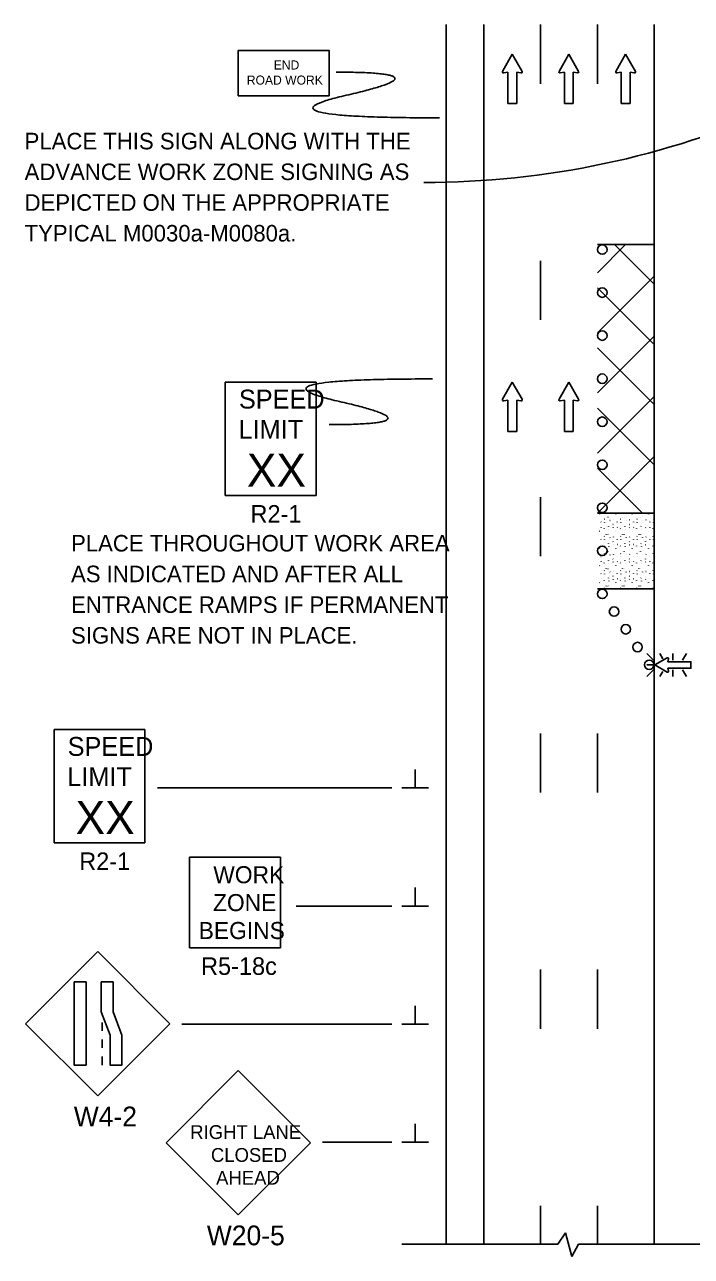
# Model space of a CAD drawing. Extents: x 16774 to 18475, y 7218 to 8206.
# Drawn here: x 16774 to 17056, y 7680 to 8201 of the extents above; entities that cross this region are included whole.
import ezdxf

# ---------------------------------------------------------------- set-up
doc = ezdxf.new("R2010")
doc.units = 0
for name, color, linetype in [('ALI_LEGAL_EX', 7, 'Continuous'), ('MT_SCRATCH_LEVEL_E', 7, 'Continuous'), ('PAVT_EDGE_EX', 7, 'Continuous'), ('TRAFFIC_SIGNS_PR', 7, 'Continuous'), ('TYPICAL_TEXT_DIMEN_PR', 7, 'Continuous')]:
    doc.layers.add(name, color=color, linetype=linetype)

msp = doc.modelspace()

# ---------------------------------------------------------------- linework, layer by layer
at = {"layer": 'ALI_LEGAL_EX'}
for points in [[(16992.01, 8201.21), (16992.01, 8176.21)], [(17016.01, 8201.21), (17016.01, 8176.21)], [(16992.01, 8101.21), (16992.01, 8076.21)], [(16992.01, 8001.21), (16992.01, 7976.21)], [(16992.01, 7901.21), (16992.01, 7876.21)], [(17016.01, 7901.21), (17016.01, 7876.21)], [(16992.01, 7801.21), (16992.01, 7776.21)], [(17016.01, 7801.21), (17016.01, 7776.21)], [(16992.01, 7701.21), (16992.01, 7684.99)], [(17016.01, 7701.21), (17016.01, 7684.99)]]:
    msp.add_lwpolyline(points, dxfattribs=at)
at = {"layer": 'MT_SCRATCH_LEVEL_E'}
for p, q in [((16980.01, 8188.68), (16975.89, 8181.44)), ((16984.15, 8181.44), (16980.01, 8188.68)), ((17003.91, 8188.68), (16999.8, 8181.44)), ((17008.06, 8181.44), (17003.91, 8188.68)), ((17027.96, 8188.68), (17023.85, 8181.44)), ((17032.11, 8181.44), (17027.96, 8188.68)), ((16976.38, 8180.75), (16978.15, 8181.07)), ((16978.15, 8181.07), (16978.15, 8167.81)), ((16981.9, 8167.81), (16981.9, 8181.07)), ((16981.9, 8181.07), (16983.67, 8180.75)), ((17000.28, 8180.75), (17002.06, 8181.07)), ((17002.06, 8181.07), (17002.06, 8167.81)), ((17005.8, 8167.81), (17005.8, 8181.07)), ((17005.8, 8181.07), (17007.58, 8180.75)), ((17024.33, 8180.75), (17026.11, 8181.07)), ((17026.11, 8181.07), (17026.11, 8167.81)), ((17029.85, 8167.81), (17029.85, 8181.07)), ((17029.85, 8181.07), (17031.63, 8180.75)), ((16978.15, 8167.81), (16981.9, 8167.81)), ((17002.06, 8167.81), (17005.8, 8167.81)), ((17026.11, 8167.81), (17029.85, 8167.81)), ((16980.01, 8049.9), (16975.89, 8042.66)), ((16984.15, 8042.66), (16980.01, 8049.9)), ((17003.91, 8049.9), (16999.8, 8042.66)), ((17008.06, 8042.66), (17003.91, 8049.9)), ((16976.38, 8041.98), (16978.15, 8042.29)), ((16978.15, 8042.29), (16978.15, 8029.04)), ((16981.9, 8029.04), (16981.9, 8042.29)), ((16981.9, 8042.29), (16983.67, 8041.98)), ((17000.28, 8041.98), (17002.06, 8042.29)), ((17002.06, 8042.29), (17002.06, 8029.04)), ((17005.8, 8029.04), (17005.8, 8042.29)), ((17005.8, 8042.29), (17007.58, 8041.98)), ((16978.15, 8029.04), (16981.9, 8029.04)), ((17002.06, 8029.04), (17005.8, 8029.04))]:
    msp.add_line(p, q, dxfattribs=at)
for centre, start, end in [((16976.3, 8181.21), 150.4248, 279.9638), ((16983.74, 8181.21), 260.0362, 29.7731), ((17000.21, 8181.21), 150.4248, 279.9638), ((17007.65, 8181.21), 260.0362, 29.7731), ((17024.26, 8181.21), 150.4248, 279.9638), ((17031.7, 8181.21), 260.0362, 29.7731), ((16976.3, 8042.44), 150.4248, 279.9638), ((16983.74, 8042.44), 260.0362, 29.7731), ((17000.21, 8042.44), 150.4248, 279.9638), ((17007.65, 8042.44), 260.0362, 29.7731)]:
    msp.add_arc(centre, 0.463, start, end, dxfattribs=at)
at = {"layer": 'PAVT_EDGE_EX'}
for p, q in [((16952.01, 8201.21), (16952.01, 7684.99)), ((16968.01, 8201.21), (16968.01, 7684.99)), ((17040.01, 8201.21), (17040.01, 7684.99)), ((17040.01, 8108.12), (17016.01, 8108.12)), ((17016.01, 8108.12), (17040.01, 8108.12)), ((17016.01, 8096.22), (17027.91, 8108.12)), ((17040.01, 8091.31), (17023.2, 8108.12)), ((17040.01, 7994.39), (17040.01, 8108.12)), ((17016.01, 8070.76), (17040.01, 8094.76)), ((17040.01, 8065.85), (17016.01, 8089.85)), ((17016.01, 8045.3), (17040.01, 8069.3)), ((17040.01, 8040.4), (17016.01, 8064.4)), ((17016.01, 8019.85), (17040.01, 8043.85)), ((17040.01, 8014.94), (17016.01, 8038.94)), ((17016.01, 7994.39), (17040.01, 8018.39)), ((17035.1, 7994.39), (17016.01, 8013.48)), ((17016.01, 7994.39), (17040.01, 7994.39)), ((17016.01, 7994.39), (17040.01, 7994.39)), ((17040.01, 7994.39), (17016.01, 7994.39)), ((17016.01, 7994.39), (17016.01, 7994.39)), ((17016.93, 7994.03), (17016.99, 7994.15)), ((17019.72, 7992.8), (17019.77, 7992.72)), ((17020.45, 7992.77), (17020.51, 7992.69)), ((17023.82, 7994.03), (17023.87, 7994.15)), ((17026.6, 7992.8), (17026.66, 7992.72)), ((17027.34, 7992.77), (17027.39, 7992.69)), ((17030.71, 7994.03), (17030.76, 7994.15)), ((17033.49, 7992.8), (17033.54, 7992.72)), ((17034.23, 7992.77), (17034.28, 7992.69)), ((17037.6, 7994.03), (17037.65, 7994.15)), ((17040.01, 7962.33), (17040.01, 7994.39)), ((17017.5, 7990.71), (17017.56, 7990.63)), ((17017.55, 7988.5), (17017.6, 7988.42)), ((17018.83, 7987.93), (17018.85, 7987.81)), ((17018.95, 7991.84), (17019.01, 7991.95)), ((17019.03, 7990.57), (17019.08, 7990.49)), ((17020.67, 7988.78), (17020.73, 7988.9)), ((17020.86, 7987.58), (17020.92, 7987.51)), ((17021.32, 7991.39), (17021.38, 7991.31)), ((17022.6, 7989.65), (17022.65, 7989.57)), ((17022.64, 7988.25), (17022.69, 7988.37)), ((17022.77, 7991.54), (17022.82, 7991.66)), ((17024.39, 7990.71), (17024.44, 7990.63)), ((17024.44, 7988.5), (17024.49, 7988.42)), ((17025.72, 7987.93), (17025.73, 7987.81)), ((17025.84, 7991.84), (17025.89, 7991.95)), ((17025.92, 7990.57), (17025.97, 7990.49)), ((17027.56, 7988.78), (17027.61, 7988.9)), ((17027.75, 7987.58), (17027.8, 7987.51)), ((17028.21, 7991.39), (17028.26, 7991.31)), ((17029.49, 7989.65), (17029.54, 7989.57)), ((17029.53, 7988.25), (17029.58, 7988.37)), ((17029.66, 7991.54), (17029.71, 7991.66)), ((17031.28, 7990.71), (17031.33, 7990.63)), ((17031.33, 7988.5), (17031.38, 7988.42)), ((17032.61, 7987.93), (17032.62, 7987.81)), ((17032.73, 7991.84), (17032.78, 7991.95)), ((17032.81, 7990.57), (17032.86, 7990.49)), ((17034.45, 7988.78), (17034.5, 7988.9)), ((17034.64, 7987.58), (17034.69, 7987.51)), ((17035.1, 7991.39), (17035.15, 7991.31)), ((17036.38, 7989.65), (17036.43, 7989.57)), ((17036.42, 7988.25), (17036.47, 7988.37)), ((17036.55, 7991.54), (17036.6, 7991.66)), ((17038.17, 7990.71), (17038.22, 7990.63)), ((17038.21, 7988.5), (17038.27, 7988.42)), ((17039.5, 7987.93), (17039.51, 7987.81)), ((17039.62, 7991.84), (17039.67, 7991.95)), ((17039.7, 7990.57), (17039.75, 7990.49)), ((17016.93, 7986.75), (17016.99, 7986.87)), ((17017.5, 7983.43), (17017.56, 7983.35)), ((17018.95, 7984.55), (17019.01, 7984.67)), ((17019.03, 7983.29), (17019.08, 7983.21)), ((17019.72, 7985.51), (17019.77, 7985.44)), ((17020.45, 7985.48), (17020.51, 7985.4)), ((17021.32, 7984.1), (17021.38, 7984.03)), ((17022.6, 7982.37), (17022.65, 7982.29)), ((17022.77, 7984.26), (17022.82, 7984.37)), ((17023.82, 7986.75), (17023.87, 7986.87)), ((17024.39, 7983.43), (17024.44, 7983.35)), ((17025.84, 7984.55), (17025.89, 7984.67)), ((17025.92, 7983.29), (17025.97, 7983.21)), ((17026.6, 7985.51), (17026.66, 7985.44)), ((17027.34, 7985.48), (17027.39, 7985.4)), ((17028.21, 7984.1), (17028.26, 7984.03)), ((17029.49, 7982.37), (17029.54, 7982.29)), ((17029.66, 7984.26), (17029.71, 7984.37)), ((17030.71, 7986.75), (17030.76, 7986.87)), ((17031.28, 7983.43), (17031.33, 7983.35)), ((17032.73, 7984.55), (17032.78, 7984.67)), ((17032.81, 7983.29), (17032.86, 7983.21)), ((17033.49, 7985.51), (17033.54, 7985.44)), ((17034.23, 7985.48), (17034.28, 7985.4)), ((17035.1, 7984.1), (17035.15, 7984.03)), ((17036.38, 7982.37), (17036.43, 7982.29)), ((17036.55, 7984.26), (17036.6, 7984.37)), ((17037.6, 7986.75), (17037.65, 7986.87)), ((17038.17, 7983.43), (17038.22, 7983.35)), ((17039.62, 7984.55), (17039.67, 7984.67)), ((17039.7, 7983.29), (17039.75, 7983.21)), ((17016.93, 7979.46), (17016.99, 7979.58)), ((17017.55, 7981.22), (17017.6, 7981.14)), ((17018.83, 7980.64), (17018.85, 7980.52)), ((17018.95, 7977.27), (17019.01, 7977.38)), ((17019.72, 7978.23), (17019.77, 7978.15)), ((17020.45, 7978.2), (17020.51, 7978.12)), ((17020.67, 7981.5), (17020.73, 7981.61)), ((17020.86, 7980.3), (17020.92, 7980.22)), ((17022.64, 7980.97), (17022.69, 7981.08)), ((17022.77, 7976.97), (17022.82, 7977.09)), ((17023.82, 7979.46), (17023.87, 7979.58)), ((17024.44, 7981.22), (17024.49, 7981.14)), ((17025.72, 7980.64), (17025.73, 7980.52)), ((17025.84, 7977.27), (17025.89, 7977.38)), ((17026.6, 7978.23), (17026.66, 7978.15)), ((17027.34, 7978.2), (17027.39, 7978.12)), ((17027.56, 7981.5), (17027.61, 7981.61)), ((17027.75, 7980.3), (17027.8, 7980.22)), ((17029.53, 7980.97), (17029.58, 7981.08)), ((17029.66, 7976.97), (17029.71, 7977.09)), ((17030.71, 7979.46), (17030.76, 7979.58)), ((17031.33, 7981.22), (17031.38, 7981.14)), ((17032.61, 7980.64), (17032.62, 7980.52)), ((17032.73, 7977.27), (17032.78, 7977.38)), ((17033.49, 7978.23), (17033.54, 7978.15)), ((17034.23, 7978.2), (17034.28, 7978.12)), ((17034.45, 7981.5), (17034.5, 7981.61)), ((17034.64, 7980.3), (17034.69, 7980.22)), ((17036.42, 7980.97), (17036.47, 7981.08)), ((17036.55, 7976.97), (17036.6, 7977.09)), ((17037.6, 7979.46), (17037.65, 7979.58)), ((17038.21, 7981.22), (17038.27, 7981.14)), ((17039.5, 7980.64), (17039.51, 7980.52)), ((17039.62, 7977.27), (17039.67, 7977.38)), ((17016.93, 7972.18), (17016.99, 7972.3)), ((17017.5, 7976.14), (17017.56, 7976.06)), ((17017.55, 7973.93), (17017.6, 7973.85)), ((17018.83, 7973.36), (17018.85, 7973.24)), ((17019.03, 7976), (17019.08, 7975.92)), ((17020.67, 7974.21), (17020.73, 7974.33)), ((17020.86, 7973.01), (17020.92, 7972.94)), ((17021.32, 7976.82), (17021.38, 7976.74)), ((17022.6, 7975.08), (17022.65, 7975)), ((17022.64, 7973.68), (17022.69, 7973.8)), ((17023.82, 7972.18), (17023.87, 7972.3)), ((17024.39, 7976.14), (17024.44, 7976.06)), ((17024.44, 7973.93), (17024.49, 7973.85)), ((17025.72, 7973.36), (17025.73, 7973.24)), ((17025.92, 7976), (17025.97, 7975.92)), ((17027.56, 7974.21), (17027.61, 7974.33)), ((17027.75, 7973.01), (17027.8, 7972.94)), ((17028.21, 7976.82), (17028.26, 7976.74)), ((17029.49, 7975.08), (17029.54, 7975)), ((17029.53, 7973.68), (17029.58, 7973.8)), ((17030.71, 7972.18), (17030.76, 7972.3)), ((17031.28, 7976.14), (17031.33, 7976.06)), ((17031.33, 7973.93), (17031.38, 7973.85)), ((17032.61, 7973.36), (17032.62, 7973.24)), ((17032.81, 7976), (17032.86, 7975.92)), ((17034.45, 7974.21), (17034.5, 7974.33)), ((17034.64, 7973.01), (17034.69, 7972.94)), ((17035.1, 7976.82), (17035.15, 7976.74)), ((17036.38, 7975.08), (17036.43, 7975)), ((17036.42, 7973.68), (17036.47, 7973.8)), ((17037.6, 7972.18), (17037.65, 7972.3)), ((17038.17, 7976.14), (17038.22, 7976.06)), ((17038.21, 7973.93), (17038.27, 7973.85)), ((17039.5, 7973.36), (17039.51, 7973.24)), ((17039.7, 7976), (17039.75, 7975.92)), ((17017.5, 7968.86), (17017.56, 7968.78)), ((17017.55, 7966.65), (17017.6, 7966.57)), ((17018.95, 7969.98), (17019.01, 7970.1)), ((17019.03, 7968.72), (17019.08, 7968.64)), ((17019.72, 7970.94), (17019.77, 7970.86)), ((17020.45, 7970.91), (17020.51, 7970.84)), ((17020.67, 7966.93), (17020.73, 7967.04)), ((17021.32, 7969.53), (17021.38, 7969.46)), ((17022.6, 7967.8), (17022.65, 7967.72)), ((17022.64, 7966.4), (17022.69, 7966.51)), ((17022.77, 7969.69), (17022.82, 7969.8)), ((17024.39, 7968.86), (17024.44, 7968.78)), ((17024.44, 7966.65), (17024.49, 7966.57)), ((17025.84, 7969.98), (17025.89, 7970.1)), ((17025.92, 7968.72), (17025.97, 7968.64)), ((17026.6, 7970.94), (17026.66, 7970.86)), ((17027.34, 7970.91), (17027.39, 7970.84)), ((17027.56, 7966.93), (17027.61, 7967.04)), ((17028.21, 7969.53), (17028.26, 7969.46)), ((17029.49, 7967.8), (17029.54, 7967.72)), ((17029.53, 7966.4), (17029.58, 7966.51)), ((17029.66, 7969.69), (17029.71, 7969.8)), ((17031.28, 7968.86), (17031.33, 7968.78)), ((17031.33, 7966.65), (17031.38, 7966.57)), ((17032.73, 7969.98), (17032.78, 7970.1)), ((17032.81, 7968.72), (17032.86, 7968.64)), ((17033.49, 7970.94), (17033.54, 7970.86)), ((17034.23, 7970.91), (17034.28, 7970.84)), ((17034.45, 7966.93), (17034.5, 7967.04)), ((17035.1, 7969.53), (17035.15, 7969.46)), ((17036.38, 7967.8), (17036.43, 7967.72)), ((17036.42, 7966.4), (17036.47, 7966.51)), ((17036.55, 7969.69), (17036.6, 7969.8)), ((17038.17, 7968.86), (17038.22, 7968.78)), ((17038.21, 7966.65), (17038.27, 7966.57)), ((17039.62, 7969.98), (17039.67, 7970.1)), ((17039.7, 7968.72), (17039.75, 7968.64)), ((17016.01, 7962.33), (17040.01, 7962.33)), ((17016.01, 7962.33), (17040.01, 7962.33)), ((17016.93, 7964.89), (17016.99, 7965.01)), ((17018.83, 7966.07), (17018.85, 7965.95)), ((17018.95, 7962.7), (17019.01, 7962.81)), ((17019.72, 7963.66), (17019.77, 7963.58)), ((17020.45, 7963.63), (17020.51, 7963.55)), ((17020.86, 7965.73), (17020.92, 7965.65)), ((17022.77, 7962.4), (17022.82, 7962.52)), ((17023.82, 7964.89), (17023.87, 7965.01)), ((17025.72, 7966.07), (17025.73, 7965.95)), ((17025.84, 7962.7), (17025.89, 7962.81)), ((17026.6, 7963.66), (17026.66, 7963.58)), ((17027.34, 7963.63), (17027.39, 7963.55)), ((17027.75, 7965.73), (17027.8, 7965.65)), ((17029.66, 7962.4), (17029.71, 7962.52)), ((17030.71, 7964.89), (17030.76, 7965.01)), ((17032.61, 7966.07), (17032.62, 7965.95)), ((17032.73, 7962.7), (17032.78, 7962.81)), ((17033.49, 7963.66), (17033.54, 7963.58)), ((17034.23, 7963.63), (17034.28, 7963.55)), ((17034.64, 7965.73), (17034.69, 7965.65)), ((17036.55, 7962.4), (17036.6, 7962.52)), ((17037.6, 7964.89), (17037.65, 7965.01)), ((17039.5, 7966.07), (17039.51, 7965.95)), ((17039.62, 7962.7), (17039.67, 7962.81))]:
    msp.add_line(p, q, dxfattribs=at)
at = {"layer": 'TRAFFIC_SIGNS_PR'}
for p, q in [((16858.56, 8049.85), (16896.96, 8049.85)), ((16858.56, 8001.85), (16858.56, 8049.85)), ((16896.96, 8001.85), (16896.96, 8049.85)), ((16858.56, 8001.85), (16896.96, 8001.85)), ((17037, 7935.03), (17039.81, 7932.21)), ((17039.81, 7930.18), (17037, 7930.18)), ((17043.72, 7932.84), (17042.46, 7935.03)), ((17047.9, 7932.21), (17047.9, 7935.03)), ((17052.03, 7932.21), (17053.66, 7935.03)), ((17037, 7925.32), (17039.81, 7928.14)), ((17042.43, 7925.32), (17043.64, 7927.42)), ((17047.9, 7928.14), (17047.9, 7925.32)), ((17053.69, 7925.32), (17052.06, 7928.14)), ((16786.11, 7902.82), (16824.51, 7902.82)), ((16786.11, 7854.82), (16786.11, 7902.82)), ((16824.51, 7854.82), (16824.51, 7902.82)), ((16786.11, 7854.82), (16824.51, 7854.82)), ((16843.5, 7810.42), (16843.5, 7848.82)), ((16843.5, 7848.82), (16881.9, 7848.82)), ((16881.9, 7810.42), (16881.9, 7848.82)), ((16843.5, 7810.42), (16881.9, 7810.42)), ((16804.64, 7808.84), (16774.09, 7778.29)), ((16835.18, 7778.29), (16804.64, 7808.84)), ((16806.48, 7778.85), (16806.48, 7775.25)), ((16774.09, 7778.29), (16804.64, 7747.75)), ((16804.64, 7747.75), (16835.18, 7778.29)), ((16806.48, 7771.65), (16806.48, 7768.05)), ((16806.48, 7764.45), (16806.48, 7760.85)), ((16864.07, 7758.51), (16833.53, 7727.96)), ((16894.62, 7727.96), (16864.07, 7758.51)), ((16833.53, 7727.96), (16864.07, 7697.41)), ((16864.07, 7697.41), (16894.62, 7727.96))]:
    msp.add_line(p, q, dxfattribs=at)
for points in [[(16864.06, 8171.09), (16902.47, 8171.09), (16902.47, 8190.29), (16864.06, 8190.29)], [(16794.63, 7796), (16794.63, 7760.85), (16799.69, 7760.85), (16799.69, 7796)], [(16806.03, 7796), (16806.03, 7783.42), (16809.8, 7773.42), (16809.8, 7760.85), (16814.85, 7760.85), (16814.85, 7773.42), (16811.09, 7783.42), (16811.09, 7796)]]:
    msp.add_lwpolyline(points, close=True, dxfattribs=at)
for points in [[(17045.57, 7933.19), (17040.26, 7930.18), (17045.57, 7927.13)], [(17046.07, 7927.49), (17045.84, 7928.79), (17055.57, 7928.79), (17055.57, 7931.53), (17045.84, 7931.53), (17046.08, 7932.84)]]:
    msp.add_lwpolyline(points, dxfattribs=at)
for centre in [(17018.1, 8106), (17018.1, 8087.78), (17018.1, 8069.57), (17018.1, 8051.35), (17018.1, 8033.14), (17018.1, 8014.92), (17018.1, 7996.71), (17018.1, 7978.5), (17018.1, 7960.28), (17023.07, 7952.77), (17028.04, 7945.27), (17033.01, 7937.76), (17037.98, 7930.26)]:
    msp.add_circle(centre, 2, dxfattribs=at)
for centre, radius, start, end in [((16942.96, 8500.8), 366.4, 269.9454, 293.9907), ((17045.74, 7932.89), 0.341, 350.7308, 118.8916), ((17045.74, 7927.43), 0.341, 241.4833, 9.9593)]:
    msp.add_arc(centre, radius, start, end, dxfattribs=at)
for points in [[(16905.5, 8181.1), (16952.74, 8181.1), (16867.72, 8161.75), (16949.19, 8161.75)], [(16902.58, 8031.91), (16949.82, 8031.91), (16864.79, 8051.25), (16946.27, 8051.25)]]:
    msp.add_open_spline(points, degree=2, dxfattribs=at)
at = {"layer": 'TYPICAL_TEXT_DIMEN_PR'}
for p, q in [((16938.88, 7878.14), (16938.88, 7885.93)), ((16829.91, 7878.14), (16929.01, 7878.14)), ((16933.26, 7878.14), (16944.51, 7878.14)), ((16938.88, 7828.14), (16938.88, 7835.93)), ((16888.62, 7828.14), (16929.01, 7828.14)), ((16933.26, 7828.14), (16944.51, 7828.14)), ((16938.88, 7778.14), (16938.88, 7785.93)), ((16840.16, 7778.14), (16929.01, 7778.14)), ((16933.26, 7778.14), (16944.51, 7778.14)), ((16938.88, 7728.14), (16938.88, 7735.93)), ((16899.75, 7728.14), (16929.01, 7728.14)), ((16933.26, 7728.14), (16944.51, 7728.14)), ((16999.26, 7684.99), (16933.32, 7684.99)), ((17002.52, 7689.79), (16999.26, 7684.99)), ((17005.26, 7679.85), (17002.52, 7689.79)), ((17008, 7684.99), (17005.26, 7679.85)), ((17070.34, 7684.99), (17008, 7684.99))]:
    msp.add_line(p, q, dxfattribs=at)

# ---------------------------------------------------------------- texts
at = {"layer": 'TRAFFIC_SIGNS_PR'}
for s, height, p in [('END', 3.831, (16879.07, 8182.22)), ('ROAD WORK', 3.831, (16867.68, 8175.83)), ('PLACE THIS SIGN ALONG WITH THE', 7, (16773.66, 8148.42)), ('ADVANCE WORK ZONE SIGNING AS', 7, (16773.66, 8135.42)), ('DEPICTED ON THE APPROPRIATE', 7, (16773.66, 8122.42)), ('TYPICAL M0030a-M0080a.', 7, (16773.66, 8109.42)), ('SPEED', 8, (16864.33, 8038.71)), ('LIMIT', 8, (16864.17, 8025.91)), ('XX', 14.031, (16867.68, 8005.61)), ('R2-1', 7.44, (16869.24, 7990.41)), ('PLACE THROUGHOUT WORK AREA', 7, (16793.31, 7978.21)), ('AS INDICATED AND AFTER ALL', 7, (16793.31, 7965.21)), ('ENTRANCE RAMPS IF PERMANENT', 7, (16793.31, 7952.21)), ('SIGNS ARE NOT IN PLACE.', 7, (16793.31, 7939.21)), ('SPEED', 8, (16791.87, 7891.69)), ('LIMIT', 8, (16791.71, 7878.89)), ('XX', 14.031, (16795.22, 7858.58)), ('R2-1', 7.44, (16796.78, 7843.38)), ('WORK', 7.217, (16853.5, 7837.79)), ('ZONE', 7.217, (16853.38, 7825.98)), ('BEGINS', 7.217, (16847.31, 7814.17)), ('R5-18c', 7.44, (16848.31, 7798.99)), ('W4-2', 8.37, (16794.47, 7734.88)), ('RIGHT LANE', 5.85, (16843.73, 7729.53)), ('CLOSED', 5.85, (16852.5, 7719.85)), ('AHEAD', 5.85, (16854.69, 7710.18)), ('W20-5', 8.37, (16850.77, 7684.54))]:
    msp.add_text(s, height=height, dxfattribs=at).set_placement(p)

doc.saveas('drawing.dxf')
